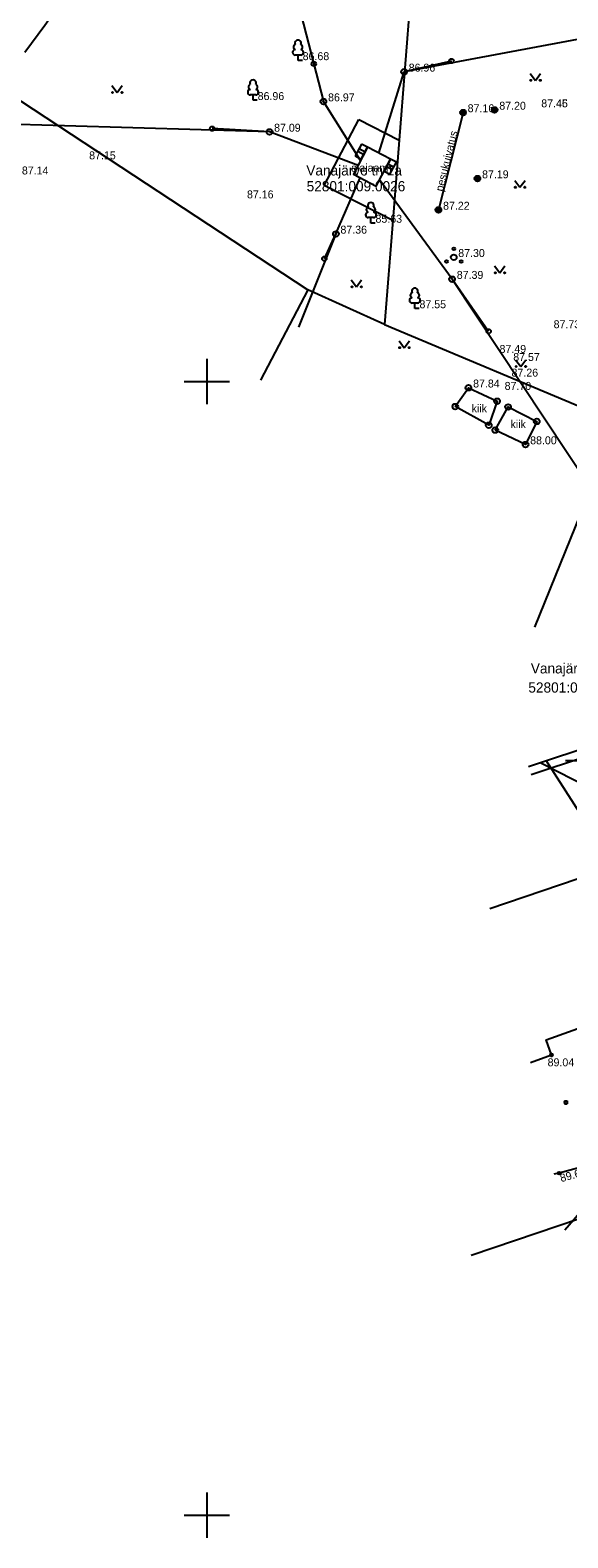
# Model space of a CAD drawing. Extents: x 648748 to 649126, y 6457789 to 6458252.
# Drawn here: x 648884.4 to 648931.8, y 6457948 to 6458081 of the extents above; entities that cross this region are included whole.
import ezdxf

# ---------------------------------------------------------------- set-up
doc = ezdxf.new("R2010")
doc.units = 0
for name, color, linetype in [('AED', 7, 'Continuous'), ('ELRAJATISMP', 7, 'Continuous'), ('HALJASTUS', 7, 'Continuous'), ('HOONE', 7, 'Continuous'), ('HOONEDET', 7, 'Continuous'), ('KORGUS-EH2000', 7, 'Continuous'), ('KPOHULIIN', 7, 'Continuous'), ('MPOHULIIN', 7, 'Continuous'), ('PIIR', 7, 'Continuous'), ('POST', 7, 'Continuous'), ('PUU', 7, 'Continuous'), ('RAJATIS', 7, 'Continuous'), ('RAJATISEDET', 7, 'Continuous'), ('SIOHULIIN', 7, 'Continuous'), ('SITRASS', 7, 'Continuous'), ('TEE', 7, 'Continuous'), ('TRUUP', 7, 'Continuous'), ('VORK', 7, 'Continuous'), ('VTRASS', 7, 'Continuous')]:
    doc.layers.add(name, color=color, linetype=linetype)

msp = doc.modelspace()

# ---------------------------------------------------------------- linework, layer by layer
at = {"layer": 'AED'}
for p, q in [((648931.54, 6457986.54), (648931.54, 6457986.29)), ((648931.54, 6457986.54), (648931.79, 6457986.54)), ((648931.79, 6457986.54), (648931.79, 6457986.29)), ((648931.54, 6457986.29), (648931.79, 6457986.29))]:
    msp.add_line(p, q, dxfattribs=at)
at = {"layer": 'ELRAJATISMP'}
for p, q in [((648913.66, 6458070.93), (648913.1, 6458069.88)), ((648913.32, 6458070.29), (648913.84, 6458070.01)), ((648913.44, 6458070.53), (648913.97, 6458070.25)), ((648913.63, 6458069.6), (648914.19, 6458070.66)), ((648914.19, 6458070.66), (648913.66, 6458070.93)), ((648913.1, 6458069.88), (648913.63, 6458069.6)), ((648916.19, 6458069.61), (648915.64, 6458068.55)), ((648915.85, 6458068.96), (648916.38, 6458068.68)), ((648915.98, 6458069.2), (648916.51, 6458068.92)), ((648916.16, 6458068.27), (648916.72, 6458069.33)), ((648916.72, 6458069.33), (648916.19, 6458069.61)), ((648915.64, 6458068.55), (648916.16, 6458068.27))]:
    msp.add_line(p, q, dxfattribs=at)
at = {"layer": 'HALJASTUS'}
for p, q in [((648928.52, 6458077.15), (648928.98, 6458076.55)), ((648928.98, 6458076.55), (648929.42, 6458077.15)), ((648891.62, 6458076.08), (648892.09, 6458075.48)), ((648892.09, 6458075.48), (648892.53, 6458076.08)), ((648927.16, 6458067.73), (648927.62, 6458067.12)), ((648927.62, 6458067.12), (648928.07, 6458067.73)), ((648925.38, 6458060.18), (648925.84, 6458059.57)), ((648925.84, 6458059.57), (648926.29, 6458060.18)), ((648912.75, 6458058.95), (648913.21, 6458058.34)), ((648913.21, 6458058.34), (648913.66, 6458058.95)), ((648916.96, 6458053.58), (648917.42, 6458052.97)), ((648917.42, 6458052.97), (648917.87, 6458053.58)), ((648927.23, 6458051.91), (648927.69, 6458051.31)), ((648927.69, 6458051.31), (648928.13, 6458051.91))]:
    msp.add_line(p, q, dxfattribs=at)
for centre in [(648891.69, 6458075.48), (648892.52, 6458075.48), (648928.58, 6458076.55), (648929.41, 6458076.55), (648927.22, 6458067.12), (648928.05, 6458067.12), (648925.44, 6458059.57), (648926.27, 6458059.57), (648912.81, 6458058.34), (648913.64, 6458058.34), (648917.02, 6458052.97), (648917.85, 6458052.97), (648927.29, 6458051.31), (648928.12, 6458051.31)]:
    msp.add_circle(centre, 0.055, dxfattribs=at)
at = {"layer": 'HOONE'}
for points in [[(648914.94, 6458067.21), (648916.19, 6458069.6), (648914.18, 6458070.66), (648912.93, 6458068.26), (648914.94, 6458067.21)], [(648928.37, 6458016.04), (648947.08, 6458022.23), (648944.13, 6458031.15), (648939.14, 6458029.5), (648938.72, 6458030.77), (648935.44, 6458029.68)], [(648928.54, 6457989.92), (648930.41, 6457990.59), (648929.93, 6457991.92), (648942.16, 6457996.31), (648940.17, 6458001.85), (648933.76, 6457999.55)]]:
    msp.add_lwpolyline(points, dxfattribs=at)
at = {"layer": 'HOONEDET'}
msp.add_lwpolyline([(648928.6, 6458015.33), (648947.87, 6458021.72), (648947.38, 6458023.57), (648944.31, 6458032.67), (648939.57, 6458031.1), (648939.02, 6458032.63), (648933.93, 6458031)], dxfattribs=at)
at = {"layer": 'KORGUS-EH2000'}
for centre in [(648930.41, 6457990.59), (648931.66, 6457986.42), (648931.09, 6457980.17)]:
    msp.add_circle(centre, 0.125, dxfattribs=at)
at = {"layer": 'KPOHULIIN'}
for points in [[(648911.39, 6458063), (648913.53, 6458067.94)], [(648911.39, 6458063), (648908.1, 6458054.78)]]:
    msp.add_lwpolyline(points, dxfattribs=at)
at = {"layer": 'MPOHULIIN'}
for p, q in [((648964.57, 6458086.1), (648917.4, 6458077.3)), ((648905.54, 6458072), (648863.65, 6458073.26))]:
    msp.add_line(p, q, dxfattribs=at)
for points in [[(648879.73, 6458193.24), (648887.68, 6458162.41), (648896.68, 6458127.49), (648901.11, 6458110.28), (648910.29, 6458074.68)], [(648915.17, 6458070.14), (648917.4, 6458077.3)], [(648913.56, 6458069.47), (648910.29, 6458074.68)], [(648913.34, 6458069.05), (648905.54, 6458072)], [(648921.64, 6458059.01), (648915.24, 6458067.78)], [(648921.64, 6458059.01), (648933.86, 6458040.57)], [(648933.86, 6458040.57), (648928.89, 6458028.31)]]:
    msp.add_lwpolyline(points, dxfattribs=at)
at = {"layer": 'PIIR'}
for p, q in [((648918.81, 6458094.69), (648916.97, 6458071.27)), ((648863.67, 6458087.81), (648908.9, 6458058.08)), ((648910.35, 6458067.26), (648913.42, 6458073.09)), ((648913.42, 6458073.09), (648916.97, 6458071.27)), ((648916.97, 6458071.27), (648916.41, 6458064.19)), ((648916.41, 6458064.19), (648910.35, 6458067.26)), ((648916.41, 6458064.19), (648915.69, 6458055.02)), ((648908.9, 6458058.08), (648904.73, 6458050.12)), ((648915.69, 6458055.02), (648908.9, 6458058.08)), ((648915.69, 6458055.02), (648944.7, 6458042.8)), ((648941.03, 6457978.89), (648923.32, 6457972.89))]:
    msp.add_line(p, q, dxfattribs=at)
at = {"layer": 'POST'}
for points in [[(648921.58, 6458078.25), (648917.4, 6458077.3)], [(648909.44, 6458078), (648910.29, 6458074.68)], [(648905.54, 6458072), (648900.48, 6458072.29)], [(648910.37, 6458060.82), (648911.39, 6458063)], [(648924.86, 6458054.41), (648921.64, 6458059.01)]]:
    msp.add_lwpolyline(points, dxfattribs=at)
for centre, radius in [((648909.44, 6458078), 0.2), ((648921.58, 6458078.25), 0.2), ((648917.4, 6458077.3), 0.25), ((648910.29, 6458074.68), 0.25), ((648910.29, 6458074.68), 0.0234), ((648900.48, 6458072.29), 0.2), ((648905.54, 6458072), 0.25), ((648911.39, 6458063), 0.25), ((648911.39, 6458063), 0.0234), ((648910.37, 6458060.82), 0.2), ((648921.64, 6458059.01), 0.25), ((648924.86, 6458054.41), 0.2)]:
    msp.add_circle(centre, radius, dxfattribs=at)
at = {"layer": 'PUU'}
for p, q in [((648908.29, 6458078.78), (648907.81, 6458078.78)), ((648908.05, 6458078.31), (648908.05, 6458078.78)), ((648908.43, 6458078.31), (648908.05, 6458078.31)), ((648904.32, 6458075.26), (648903.84, 6458075.26)), ((648904.08, 6458074.79), (648904.08, 6458075.26)), ((648904.46, 6458074.79), (648904.08, 6458074.79)), ((648914.71, 6458064.44), (648914.23, 6458064.44)), ((648914.47, 6458063.96), (648914.47, 6458064.44)), ((648914.85, 6458063.96), (648914.47, 6458063.96)), ((648918.59, 6458056.9), (648918.11, 6458056.9)), ((648918.35, 6458056.42), (648918.35, 6458056.9)), ((648918.73, 6458056.42), (648918.35, 6458056.42))]:
    msp.add_line(p, q, dxfattribs=at)
for centre, radius in [((648921.78, 6458060.94), 0.25), ((648921.78, 6458061.69), 0.125), ((648921.13, 6458060.57), 0.125), ((648922.43, 6458060.57), 0.125)]:
    msp.add_circle(centre, radius, dxfattribs=at)
for centre, radius, start, end in [((648907.88, 6458079.48), 0.233, 109.022, 253.142), ((648908.05, 6458079.83), 0.277, 332.58, 207.42), ((648908.22, 6458079.48), 0.233, 286.851, 70.986), ((648907.81, 6458079.02), 0.238, 90.002, 269.395), ((648908.29, 6458079.02), 0.238, 270.605, 89.998), ((648903.85, 6458075.5), 0.238, 90.002, 269.395), ((648903.91, 6458075.96), 0.233, 109.022, 253.142), ((648904.08, 6458076.31), 0.277, 332.58, 207.42), ((648904.25, 6458075.96), 0.233, 286.851, 70.986), ((648904.32, 6458075.5), 0.238, 270.605, 89.998), ((648914.24, 6458064.68), 0.238, 90.002, 269.395), ((648914.3, 6458065.14), 0.233, 109.022, 253.142), ((648914.47, 6458065.49), 0.277, 332.58, 207.42), ((648914.64, 6458065.14), 0.233, 286.851, 70.986), ((648914.71, 6458064.68), 0.238, 270.605, 89.998), ((648918.35, 6458057.95), 0.277, 332.58, 207.42), ((648918.11, 6458057.14), 0.238, 90.002, 269.395), ((648918.18, 6458057.6), 0.233, 109.022, 253.142), ((648918.52, 6458057.6), 0.233, 286.851, 70.986), ((648918.59, 6458057.14), 0.238, 270.605, 89.998)]:
    msp.add_arc(centre, radius, start, end, dxfattribs=at)
at = {"layer": 'RAJATIS'}
for points in [[(648921.92, 6458047.78), (648923.08, 6458049.43), (648925.61, 6458048.25), (648924.87, 6458046.13), (648921.92, 6458047.78)], [(648925.44, 6458045.7), (648926.58, 6458047.74), (648929.1, 6458046.46), (648928.11, 6458044.43), (648925.44, 6458045.7)]]:
    msp.add_lwpolyline(points, dxfattribs=at)
for centre, radius in [((648925.39, 6458073.94), 0.25), ((648922.6, 6458073.71), 0.25), ((648922.6, 6458073.71), 0.225), ((648922.6, 6458073.71), 0.2), ((648922.6, 6458073.71), 0.175), ((648922.6, 6458073.71), 0.15), ((648922.6, 6458073.71), 0.125), ((648922.6, 6458073.71), 0.1), ((648922.6, 6458073.71), 0.075), ((648922.6, 6458073.71), 0.05), ((648922.6, 6458073.71), 0.025), ((648925.39, 6458073.94), 0.225), ((648925.39, 6458073.94), 0.2), ((648925.39, 6458073.94), 0.175), ((648925.39, 6458073.94), 0.15), ((648925.39, 6458073.94), 0.125), ((648925.39, 6458073.94), 0.1), ((648925.39, 6458073.94), 0.075), ((648925.39, 6458073.94), 0.05), ((648925.39, 6458073.94), 0.025), ((648923.87, 6458067.89), 0.25), ((648923.87, 6458067.89), 0.225), ((648923.87, 6458067.89), 0.2), ((648923.87, 6458067.89), 0.175), ((648923.87, 6458067.89), 0.15), ((648923.87, 6458067.89), 0.125), ((648923.87, 6458067.89), 0.1), ((648923.87, 6458067.89), 0.075), ((648923.87, 6458067.89), 0.05), ((648923.87, 6458067.89), 0.025), ((648920.43, 6458065.12), 0.25), ((648920.43, 6458065.12), 0.225), ((648920.43, 6458065.12), 0.2), ((648920.43, 6458065.12), 0.175), ((648920.43, 6458065.12), 0.15), ((648920.43, 6458065.12), 0.125), ((648920.43, 6458065.12), 0.1), ((648920.43, 6458065.12), 0.075), ((648920.43, 6458065.12), 0.05), ((648920.43, 6458065.12), 0.025), ((648923.08, 6458049.43), 0.25), ((648921.92, 6458047.78), 0.25), ((648925.61, 6458048.25), 0.25), ((648926.58, 6458047.74), 0.25), ((648924.87, 6458046.13), 0.25), ((648929.1, 6458046.46), 0.25), ((648925.44, 6458045.7), 0.25), ((648928.11, 6458044.43), 0.25)]:
    msp.add_circle(centre, radius, dxfattribs=at)
at = {"layer": 'RAJATISEDET'}
msp.add_lwpolyline([(648922.6, 6458073.71), (648920.43, 6458065.12)], dxfattribs=at)
at = {"layer": 'SIOHULIIN'}
msp.add_line((648950.02, 6457985.08), (648929.94, 6458016.56), dxfattribs=at)
at = {"layer": 'SITRASS'}
for points in [[(648929.39, 6458016.38), (648935.35, 6458013.35), (648939.32, 6458010.14), (648940.45, 6458008.75)], [(648924.97, 6458003.5), (648940.38, 6458008.74), (648941.56, 6458008.85), (648943.83, 6458008.08), (648943.94, 6458007.93), (648944.28, 6458006.48), (648944.12, 6457999.61), (648944.41, 6457995.91), (648943.98, 6457992.03), (648941.91, 6457992.28), (648941.69, 6457992)], [(648943.98, 6457992.03), (648943.97, 6457991.99), (648943.63, 6457990.79), (648940.42, 6457986.54), (648936.9, 6457982.01), (648933.27, 6457977.12), (648931.58, 6457975.14)]]:
    msp.add_lwpolyline(points, dxfattribs=at)
at = {"layer": 'TEE'}
msp.add_lwpolyline([(648943.93, 6457987.91), (648943.01, 6457985.94), (648940.85, 6457983.55), (648937.01, 6457981.77), (648931.09, 6457980.17), (648930.61, 6457980.08)], dxfattribs=at)
at = {"layer": 'TRUUP'}
msp.add_lwpolyline([(648931.65, 6458016.55), (648947.4, 6458016.55), (648947.74, 6458014.34)], dxfattribs=at)
at = {"layer": 'VORK'}
for p, q in [((648900, 6458052), (648900, 6458048)), ((648898, 6458050), (648902, 6458050)), ((648900, 6457952), (648900, 6457948)), ((648898, 6457950), (648902, 6457950))]:
    msp.add_line(p, q, dxfattribs=at)
at = {"layer": 'VTRASS'}
msp.add_lwpolyline([(648910.1, 6458115.31), (648909.91, 6458115.04), (648908.47, 6458113.14), (648906.85, 6458111.04), (648905.37, 6458108.81), (648903.69, 6458106.39), (648901.92, 6458103.86), (648900, 6458101.38), (648898.2, 6458099.03), (648896.34, 6458096.49), (648894.71, 6458094.08), (648892.85, 6458091.48), (648889.26, 6458086.51), (648887.3, 6458083.69), (648885.73, 6458081.4), (648883.96, 6458079)], dxfattribs=at)

# ---------------------------------------------------------------- texts
at = {"layer": 'HOONE'}
msp.add_text('alajaam', height=0.7, dxfattribs=at).set_placement((648912.73, 6458068.49))
at = {"layer": 'KORGUS-EH2000'}
for s, p in [('86.68', (648908.46, 6458078.33)), ('86.96', (648917.81, 6458077.32)), ('86.96', (648904.49, 6458074.81)), ('86.97', (648910.7, 6458074.7)), ('87.16', (648923.01, 6458073.74)), ('87.20', (648925.8, 6458073.96)), ('87.45', (648929.5, 6458074.17)), ('87.46', (648929.5, 6458074.17)), ('87.09', (648905.94, 6458072.02)), ('87.15', (648889.63, 6458069.58)), ('87.14', (648883.7, 6458068.25)), ('87.19', (648924.28, 6458067.91)), ('87.16', (648903.55, 6458066.14)), ('87.22', (648920.84, 6458065.14)), ('87.36', (648911.79, 6458063.03)), ('85.63', (648914.88, 6458063.99)), ('87.30', (648922.18, 6458060.97)), ('87.39', (648922.05, 6458059.04)), ('87.55', (648918.76, 6458056.45)), ('87.73', (648930.59, 6458054.69)), ('87.49', (648925.82, 6458052.51)), ('87.57', (648927.03, 6458051.8)), ('87.26', (648926.88, 6458050.42)), ('87.84', (648923.49, 6458049.46)), ('87.70', (648926.27, 6458049.25)), ('88.00', (648928.52, 6458044.45)), ('89.04', (648930.06, 6457989.59))]:
    msp.add_text(s, height=0.7, dxfattribs=at).set_placement(p)
msp.add_text('89.67', height=0.7, rotation=15.1143, dxfattribs=at).set_placement((648931.26, 6457979.37))
at = {"layer": 'PIIR'}
for s, p in [('Vanajärve tn 1a', (648908.78, 6458068.16)), ('52801:009:0026', (648908.81, 6458066.76)), ('Vanajärve tn 3', (648928.58, 6458024.24)), ('52801:009:0752', (648928.36, 6458022.55))]:
    msp.add_text(s, height=0.9, dxfattribs=at).set_placement(p)
at = {"layer": 'RAJATIS'}
msp.add_text('pesukuivatus', height=0.7, rotation=76.1547, dxfattribs=at).set_placement((648920.83, 6458066.7))
for p in [(648923.36, 6458047.27), (648926.79, 6458045.88)]:
    msp.add_text('kiik', height=0.7, dxfattribs=at).set_placement(p)

doc.saveas('drawing.dxf')
